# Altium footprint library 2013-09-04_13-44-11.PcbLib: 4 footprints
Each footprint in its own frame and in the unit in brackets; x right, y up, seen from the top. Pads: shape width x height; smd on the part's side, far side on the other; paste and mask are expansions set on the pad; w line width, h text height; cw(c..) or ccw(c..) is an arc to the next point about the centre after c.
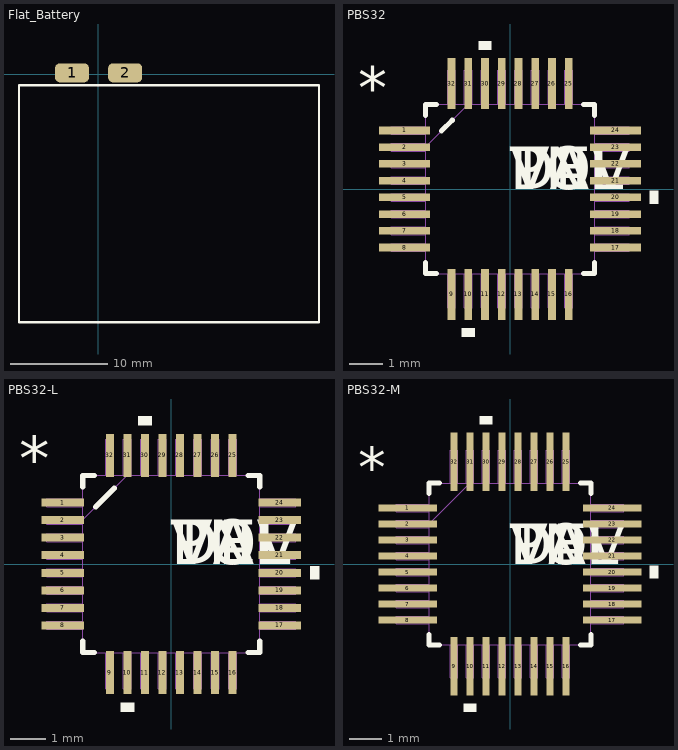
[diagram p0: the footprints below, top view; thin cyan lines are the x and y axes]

## Flat_Battery [mil]
pads (2):
  rrect50% 137.8x76.77 smd: 1(-105,5) 2(110,5)
Top Overlay:
  lines w10: -320,-1005 895,-1005 895,-45 -320,-45 -320,-1005
3D body: height 39.37, standoff 0, extent -319.98,-1004.98 894.98,-45.02

## PBS32 [mil]
pads (32):
  rect 60x9 smd: 1(-124,68.9) 2(-124,49.21) 3(-124,29.53) 4(-124,9.84) 5(-124,-9.84) 6(-124,-29.53) 7(-124,-49.21) 8(-124,-68.9) 17(124,-68.9) 18(124,-49.21) 19(124,-29.53) 20(124,-9.84) 21(124,9.84) 22(124,29.53) 23(124,49.21) 24(124,68.9)
  rect 9x60 smd: 9(-68.9,-124) 10(-49.21,-124) 11(-29.53,-124) 12(-9.84,-124) 13(9.84,-124) 14(29.53,-124) 15(49.21,-124) 16(68.9,-124) 25(68.9,124) 26(49.21,124) 27(29.53,124) 28(9.84,124) 29(-9.84,124) 30(-29.53,124) 31(-49.21,124) 32(-68.9,124)
Top Overlay:
  region: -22.03,164 -37.03,164 -37.03,174 -22.03,174
  region: 164,-2.34 174,-2.34 174,-17.34 164,-17.34
  region: -41.71,-164 -56.71,-164 -56.71,-174 -41.71,-174
  lines w6: -99.5,-86.5 -99.5,-99.5 -86.5,-99.5 ; -99.5,86.5 -99.5,99.5 -86.5,99.5 ; -80.9,68.1 -68.1,80.9 ; 86.5,-99.5 99.5,-99.5 99.5,-86.5 ; 86.5,99.5 99.5,99.5 99.5,86.5
  text "TOL" at 0,0 h50
  text "VAL" at 0,0 h50
  text "DEV" at 0,0 h50
  text "PN" at 0,0 h50
  text "*" at -179,93.74 h50
Mechanical 1:
  lines w0: -99.5,49.5 -49.5,99.5 ; -140,-73.4 -99.5,-73.4 -99.5,-64.4 -140,-64.4 -140,-73.4 ; -140,-53.71 -99.5,-53.71 -99.5,-44.71 -140,-44.71 -140,-53.71 ; -140,-34.03 -99.5,-34.03 -99.5,-25.03 -140,-25.03 -140,-34.03 ; -140,-14.34 -99.5,-14.34 -99.5,-5.34 -140,-5.34 -140,-14.34 ; -140,5.34 -99.5,5.34 -99.5,14.34 -140,14.34 -140,5.34 ; -140,25.03 -99.5,25.03 -99.5,34.03 -140,34.03 -140,25.03 ; -140,44.71 -99.5,44.71 -99.5,53.71 -140,53.71 -140,44.71 ; -140,64.4 -99.5,64.4 -99.5,73.4 -140,73.4 -140,64.4 ; -99.5,-99.5 -99.5,99.5 99.5,99.5 99.5,-99.5 -99.5,-99.5 ; -73.4,-140 -64.4,-140 -64.4,-99.5 -73.4,-99.5 -73.4,-140 ; -73.4,99.5 -73.4,140 -64.4,140 -64.4,99.5 -73.4,99.5 ; -53.71,-140 -44.71,-140 -44.71,-99.5 -53.71,-99.5 -53.71,-140 ; -53.71,99.5 -53.71,140 -44.71,140 -44.71,99.5 -53.71,99.5 ; -34.03,-140 -25.03,-140 -25.03,-99.5 -34.03,-99.5 -34.03,-140 ; -34.03,99.5 -34.03,140 -25.03,140 -25.03,99.5 -34.03,99.5 ; -14.34,-140 -5.34,-140 -5.34,-99.5 -14.34,-99.5 -14.34,-140 ; -14.34,99.5 -14.34,140 -5.34,140 -5.34,99.5 -14.34,99.5 ; 5.34,-140 14.34,-140 14.34,-99.5 5.34,-99.5 5.34,-140 ; 5.34,99.5 5.34,140 14.34,140 14.34,99.5 5.34,99.5 ; 25.03,-140 34.03,-140 34.03,-99.5 25.03,-99.5 25.03,-140 ; 25.03,99.5 25.03,140 34.03,140 34.03,99.5 25.03,99.5 ; 44.71,-140 53.71,-140 53.71,-99.5 44.71,-99.5 44.71,-140 ; 44.71,99.5 44.71,140 53.71,140 53.71,99.5 44.71,99.5 ; 64.4,-140 73.4,-140 73.4,-99.5 64.4,-99.5 64.4,-140 ; 64.4,99.5 64.4,140 73.4,140 73.4,99.5 64.4,99.5 ; 99.5,-73.4 140,-73.4 140,-64.4 99.5,-64.4 99.5,-73.4 ; 99.5,-53.71 140,-53.71 140,-44.71 99.5,-44.71 99.5,-53.71 ; 99.5,-34.03 140,-34.03 140,-25.03 99.5,-25.03 99.5,-34.03 ; 99.5,-14.34 140,-14.34 140,-5.34 99.5,-5.34 99.5,-14.34 ; 99.5,5.34 140,5.34 140,14.34 99.5,14.34 99.5,5.34 ; 99.5,25.03 140,25.03 140,34.03 99.5,34.03 99.5,25.03 ; 99.5,44.71 140,44.71 140,53.71 99.5,53.71 99.5,44.71 ; 99.5,64.4 140,64.4 140,73.4 99.5,73.4 99.5,64.4
  text "RefDes2" at 0,0 h50
  text "*" at -179,93.74 h50

## PBS32-L [mil]
pads (32):
  rect 48x9 smd: 1(-122,68.9) 2(-122,49.21) 3(-122,29.53) 4(-122,9.84) 5(-122,-9.84) 6(-122,-29.53) 7(-122,-49.21) 8(-122,-68.9) 17(122,-68.9) 18(122,-49.21) 19(122,-29.53) 20(122,-9.84) 21(122,9.84) 22(122,29.53) 23(122,49.21) 24(122,68.9)
  rect 9x48 smd: 9(-68.9,-122) 10(-49.21,-122) 11(-29.53,-122) 12(-9.84,-122) 13(9.84,-122) 14(29.53,-122) 15(49.21,-122) 16(68.9,-122) 25(68.9,122) 26(49.21,122) 27(29.53,122) 28(9.84,122) 29(-9.84,122) 30(-29.53,122) 31(-49.21,122) 32(-68.9,122)
Top Overlay:
  region: -22.03,156 -37.03,156 -37.03,166 -22.03,166
  region: 156,-2.34 166,-2.34 166,-17.34 156,-17.34
  region: -41.71,-156 -56.71,-156 -56.71,-166 -41.71,-166
  lines w6: -99.5,-86.5 -99.5,-99.5 -86.5,-99.5 ; -99.5,86.5 -99.5,99.5 -86.5,99.5 ; -84.9,64.1 -64.1,84.9 ; 86.5,-99.5 99.5,-99.5 99.5,-86.5 ; 86.5,99.5 99.5,99.5 99.5,86.5
  text "TOL" at 0,0 h50
  text "VAL" at 0,0 h50
  text "DEV" at 0,0 h50
  text "PN" at 0,0 h50
  text "*" at -171,93.74 h50
Mechanical 1:
  lines w0: -99.5,49.5 -49.5,99.5 ; -140,-73.4 -99.5,-73.4 -99.5,-64.4 -140,-64.4 -140,-73.4 ; -140,-53.71 -99.5,-53.71 -99.5,-44.71 -140,-44.71 -140,-53.71 ; -140,-34.03 -99.5,-34.03 -99.5,-25.03 -140,-25.03 -140,-34.03 ; -140,-14.34 -99.5,-14.34 -99.5,-5.34 -140,-5.34 -140,-14.34 ; -140,5.34 -99.5,5.34 -99.5,14.34 -140,14.34 -140,5.34 ; -140,25.03 -99.5,25.03 -99.5,34.03 -140,34.03 -140,25.03 ; -140,44.71 -99.5,44.71 -99.5,53.71 -140,53.71 -140,44.71 ; -140,64.4 -99.5,64.4 -99.5,73.4 -140,73.4 -140,64.4 ; -99.5,-99.5 -99.5,99.5 99.5,99.5 99.5,-99.5 -99.5,-99.5 ; -73.4,-140 -64.4,-140 -64.4,-99.5 -73.4,-99.5 -73.4,-140 ; -73.4,99.5 -73.4,140 -64.4,140 -64.4,99.5 -73.4,99.5 ; -53.71,-140 -44.71,-140 -44.71,-99.5 -53.71,-99.5 -53.71,-140 ; -53.71,99.5 -53.71,140 -44.71,140 -44.71,99.5 -53.71,99.5 ; -34.03,-140 -25.03,-140 -25.03,-99.5 -34.03,-99.5 -34.03,-140 ; -34.03,99.5 -34.03,140 -25.03,140 -25.03,99.5 -34.03,99.5 ; -14.34,-140 -5.34,-140 -5.34,-99.5 -14.34,-99.5 -14.34,-140 ; -14.34,99.5 -14.34,140 -5.34,140 -5.34,99.5 -14.34,99.5 ; 5.34,-140 14.34,-140 14.34,-99.5 5.34,-99.5 5.34,-140 ; 5.34,99.5 5.34,140 14.34,140 14.34,99.5 5.34,99.5 ; 25.03,-140 34.03,-140 34.03,-99.5 25.03,-99.5 25.03,-140 ; 25.03,99.5 25.03,140 34.03,140 34.03,99.5 25.03,99.5 ; 44.71,-140 53.71,-140 53.71,-99.5 44.71,-99.5 44.71,-140 ; 44.71,99.5 44.71,140 53.71,140 53.71,99.5 44.71,99.5 ; 64.4,-140 73.4,-140 73.4,-99.5 64.4,-99.5 64.4,-140 ; 64.4,99.5 64.4,140 73.4,140 73.4,99.5 64.4,99.5 ; 99.5,-73.4 140,-73.4 140,-64.4 99.5,-64.4 99.5,-73.4 ; 99.5,-53.71 140,-53.71 140,-44.71 99.5,-44.71 99.5,-53.71 ; 99.5,-34.03 140,-34.03 140,-25.03 99.5,-25.03 99.5,-34.03 ; 99.5,-14.34 140,-14.34 140,-5.34 99.5,-5.34 99.5,-14.34 ; 99.5,5.34 140,5.34 140,14.34 99.5,14.34 99.5,5.34 ; 99.5,25.03 140,25.03 140,34.03 99.5,34.03 99.5,25.03 ; 99.5,44.71 140,44.71 140,53.71 99.5,53.71 99.5,44.71 ; 99.5,64.4 140,64.4 140,73.4 99.5,73.4 99.5,64.4
  text "RefDes2" at 0,0 h50
  text "*" at -171,93.74 h50

## PBS32-M [mil]
pads (32):
  rect 72x9 smd: 1(-126,68.9) 2(-126,49.21) 3(-126,29.53) 4(-126,9.84) 5(-126,-9.84) 6(-126,-29.53) 7(-126,-49.21) 8(-126,-68.9) 17(126,-68.9) 18(126,-49.21) 19(126,-29.53) 20(126,-9.84) 21(126,9.84) 22(126,29.53) 23(126,49.21) 24(126,68.9)
  rect 9x72 smd: 9(-68.9,-126) 10(-49.21,-126) 11(-29.53,-126) 12(-9.84,-126) 13(9.84,-126) 14(29.53,-126) 15(49.21,-126) 16(68.9,-126) 25(68.9,126) 26(49.21,126) 27(29.53,126) 28(9.84,126) 29(-9.84,126) 30(-29.53,126) 31(-49.21,126) 32(-68.9,126)
Top Overlay:
  region: -41.71,-172 -56.71,-172 -56.71,-182 -41.71,-182
  region: 172,-2.34 182,-2.34 182,-17.34 172,-17.34
  region: -22.03,172 -37.03,172 -37.03,182 -22.03,182
  lines w6: -99.5,-86.5 -99.5,-99.5 -86.5,-99.5 ; -99.5,86.5 -99.5,99.5 -86.5,99.5 ; 86.5,-99.5 99.5,-99.5 99.5,-86.5 ; 86.5,99.5 99.5,99.5 99.5,86.5
  text "*" at -187,93.74 h50
  text "PN" at 0,0 h50
  text "DEV" at 0,0 h50
  text "VAL" at 0,0 h50
  text "TOL" at 0,0 h50
Mechanical 1:
  lines w0: -99.5,49.5 -49.5,99.5 ; -140,-73.4 -140,-64.4 -99.5,-64.4 -99.5,-73.4 -140,-73.4 ; -140,-53.71 -140,-44.71 -99.5,-44.71 -99.5,-53.71 -140,-53.71 ; -140,-34.03 -140,-25.03 -99.5,-25.03 -99.5,-34.03 -140,-34.03 ; -140,-14.34 -140,-5.34 -99.5,-5.34 -99.5,-14.34 -140,-14.34 ; -140,5.34 -140,14.34 -99.5,14.34 -99.5,5.34 -140,5.34 ; -140,25.03 -140,34.03 -99.5,34.03 -99.5,25.03 -140,25.03 ; -140,44.71 -140,53.71 -99.5,53.71 -99.5,44.71 -140,44.71 ; -140,64.4 -140,73.4 -99.5,73.4 -99.5,64.4 -140,64.4 ; -99.5,-99.5 99.5,-99.5 99.5,99.5 -99.5,99.5 -99.5,-99.5 ; -73.4,-140 -73.4,-99.5 -64.4,-99.5 -64.4,-140 -73.4,-140 ; -73.4,99.5 -64.4,99.5 -64.4,140 -73.4,140 -73.4,99.5 ; -53.71,-140 -53.71,-99.5 -44.71,-99.5 -44.71,-140 -53.71,-140 ; -53.71,99.5 -44.71,99.5 -44.71,140 -53.71,140 -53.71,99.5 ; -34.03,-140 -34.03,-99.5 -25.03,-99.5 -25.03,-140 -34.03,-140 ; -34.03,99.5 -25.03,99.5 -25.03,140 -34.03,140 -34.03,99.5 ; -14.34,-140 -14.34,-99.5 -5.34,-99.5 -5.34,-140 -14.34,-140 ; -14.34,99.5 -5.34,99.5 -5.34,140 -14.34,140 -14.34,99.5 ; 5.34,-140 5.34,-99.5 14.34,-99.5 14.34,-140 5.34,-140 ; 5.34,99.5 14.34,99.5 14.34,140 5.34,140 5.34,99.5 ; 25.03,-140 25.03,-99.5 34.03,-99.5 34.03,-140 25.03,-140 ; 25.03,99.5 34.03,99.5 34.03,140 25.03,140 25.03,99.5 ; 44.71,-140 44.71,-99.5 53.71,-99.5 53.71,-140 44.71,-140 ; 44.71,99.5 53.71,99.5 53.71,140 44.71,140 44.71,99.5 ; 64.4,-140 64.4,-99.5 73.4,-99.5 73.4,-140 64.4,-140 ; 64.4,99.5 73.4,99.5 73.4,140 64.4,140 64.4,99.5 ; 99.5,-73.4 99.5,-64.4 140,-64.4 140,-73.4 99.5,-73.4 ; 99.5,-53.71 99.5,-44.71 140,-44.71 140,-53.71 99.5,-53.71 ; 99.5,-34.03 99.5,-25.03 140,-25.03 140,-34.03 99.5,-34.03 ; 99.5,-14.34 99.5,-5.34 140,-5.34 140,-14.34 99.5,-14.34 ; 99.5,5.34 99.5,14.34 140,14.34 140,5.34 99.5,5.34 ; 99.5,25.03 99.5,34.03 140,34.03 140,25.03 99.5,25.03 ; 99.5,44.71 99.5,53.71 140,53.71 140,44.71 99.5,44.71 ; 99.5,64.4 99.5,73.4 140,73.4 140,64.4 99.5,64.4
  text "*" at -187,93.74 h50
  text "RefDes2" at 0,0 h50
